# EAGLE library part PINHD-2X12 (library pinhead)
PIN HEADER
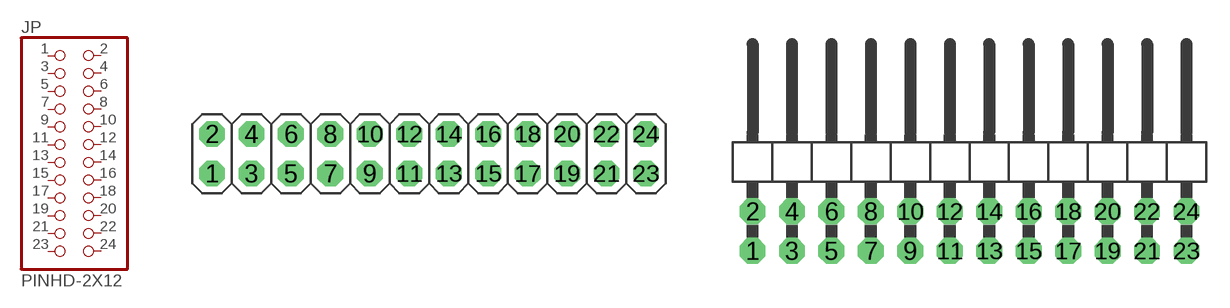
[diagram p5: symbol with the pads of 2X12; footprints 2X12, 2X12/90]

Designator prefix JP

## PINHD-2X12  [2X12]
1  1  pas
2  2  pas
3  3  pas
4  4  pas
5  5  pas
6  6  pas
7  7  pas
8  8  pas
9  9  pas
10  10  pas
11  11  pas
12  12  pas
13  13  pas
14  14  pas
15  15  pas
16  16  pas
17  17  pas
18  18  pas
19  19  pas
20  20  pas
21  21  pas
22  22  pas
23  23  pas
24  24  pas

## PINHD-2X12/90  [2X12/90]
Pads as for 2X12

## Footprint 2X12 (pad centres in mm)
PIN HEADER
drill 1.016 pad 1.67 octagon: 1 -13.97,-1.27; 2 -13.97,1.27; 3 -11.43,-1.27; 4 -11.43,1.27; 5 -8.89,-1.27; 6 -8.89,1.27; 7 -6.35,-1.27; 8 -6.35,1.27; 9 -3.81,-1.27; 10 -3.81,1.27; 11 -1.27,-1.27; 12 -1.27,1.27; 13 1.27,-1.27; 14 1.27,1.27; 15 3.81,-1.27; 16 3.81,1.27; 17 6.35,-1.27; 18 6.35,1.27; 19 8.89,-1.27; 20 8.89,1.27; 21 11.43,-1.27; 22 11.43,1.27; 23 13.97,-1.27; 24 13.97,1.27

## Footprint 2X12/90 (pad centres in mm)
PIN HEADER
drill 1.016 pad 1.67 octagon: 1 -13.97,-6.35; 2 -13.97,-3.81; 3 -11.43,-6.35; 4 -11.43,-3.81; 5 -8.89,-6.35; 6 -8.89,-3.81; 7 -6.35,-6.35; 8 -6.35,-3.81; 9 -3.81,-6.35; 10 -3.81,-3.81; 11 -1.27,-6.35; 12 -1.27,-3.81; 13 1.27,-6.35; 14 1.27,-3.81; 15 3.81,-6.35; 16 3.81,-3.81; 17 6.35,-6.35; 18 6.35,-3.81; 19 8.89,-6.35; 20 8.89,-3.81; 21 11.43,-6.35; 22 11.43,-3.81; 23 13.97,-6.35; 24 13.97,-3.81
